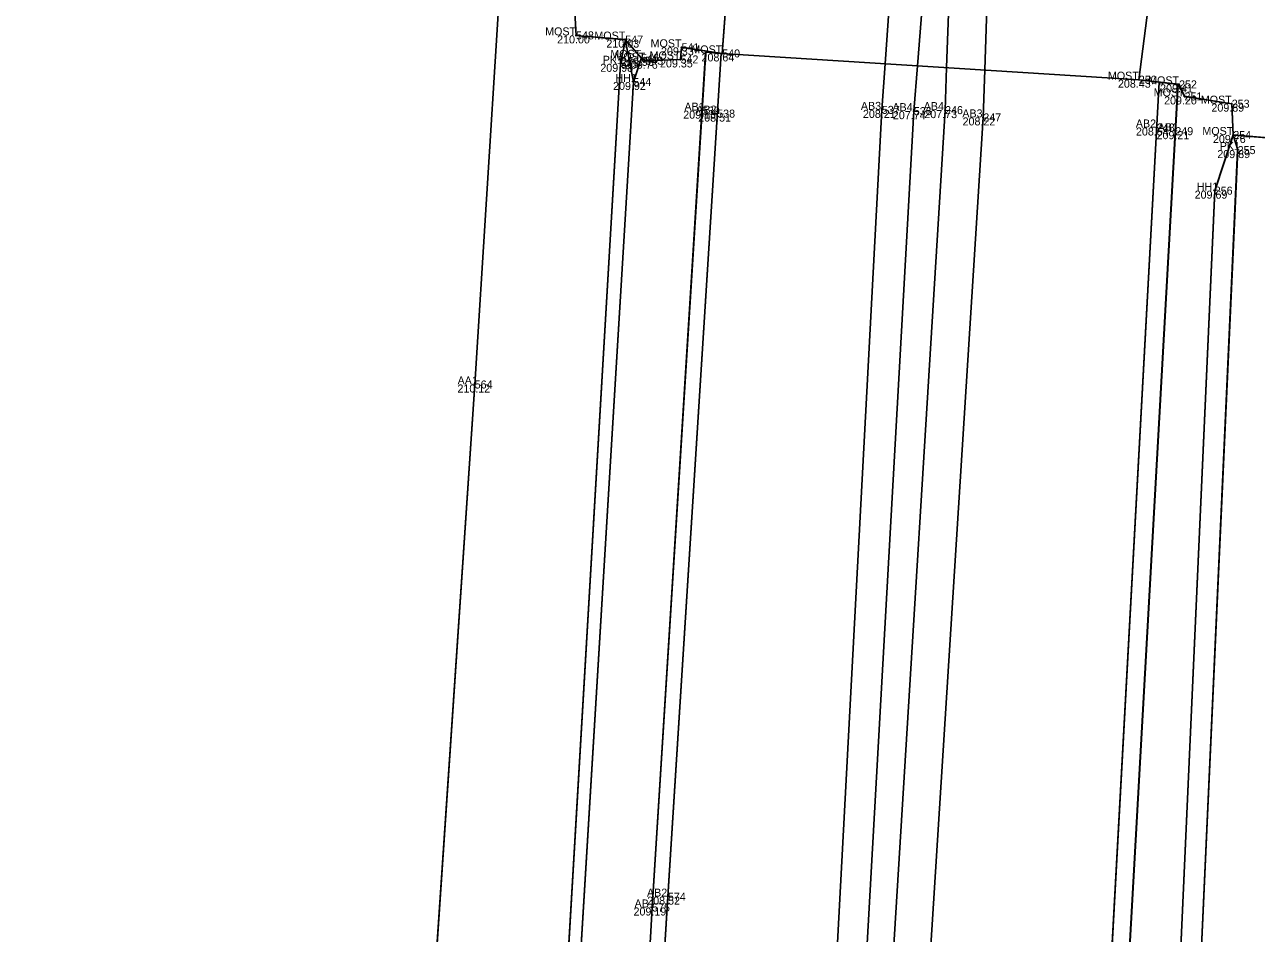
# Model space of a CAD drawing. Extents: x -263091 to -262565, y -1238731 to -1237092.
# Drawn here: x -262850.07 to -262819.29, y -1237957.59 to -1237934.9 of the extents above; entities that cross this region are included whole.
import ezdxf

# ---------------------------------------------------------------- set-up
doc = ezdxf.new("R2010")
doc.units = 0
for name, color, linetype in [('01_Hrana_betónu', 7, 'Continuous'), ('02_Oplotenie', 7, 'Continuous'), ('03_Asfalt', 7, 'Continuous'), ('04_Most', 7, 'Continuous'), ('05_Hrana_terénu', 7, 'Continuous'), ('09_Múrik', 7, 'Continuous'), ('Groma (21)', 7, 'Continuous'), ('Groma (22)', 7, 'Continuous'), ('Groma (23)', 7, 'Continuous'), ('Groma (24)', 7, 'Continuous'), ('U003_Asfalt', 7, 'Continuous'), ('U003_Betónové_múriky', 7, 'Continuous'), ('U003_Betónové_panely', 7, 'Continuous'), ('U003_Ostatné_plochy', 7, 'Continuous'), ('U003_Zeleň_mimo', 7, 'Continuous'), ('U003_Zeleň_vnútro', 7, 'Continuous'), ('U003_Zeleň_zatrávňovač', 7, 'Continuous'), ('U005_Betóny_prídavné', 7, 'Continuous')]:
    doc.layers.add(name, color=color, linetype=linetype)

msp = doc.modelspace()

# ---------------------------------------------------------------- linework, layer by layer
at = {"layer": '01_Hrana_betónu'}
for p, q in [((-262832.51, -1237933.84), (-262832.64, -1237935.62)), ((-262822.231, -1237936.276), (-262822, -1237934.47))]:
    msp.add_line(p, q, dxfattribs=at)
for points in [[(-262828.571, -1237935.876), (-262828.445, -1237934.083)], [(-262827.618, -1237934.133), (-262827.762, -1237935.927)], [(-262826.971, -1237934.173), (-262827.034, -1237935.973)], [(-262826.079, -1237936.033), (-262826.022, -1237934.23)], [(-262832.64, -1237935.62), (-262832.67, -1237935.618)], [(-262903.088, -1238238.797), (-262890.817, -1238204.479), (-262885.468, -1238189.492), (-262878.003, -1238168.56), (-262870.455, -1238147.513), (-262864.947, -1238132.168), (-262859.037, -1238116.651), (-262848.977, -1238095.826), (-262842.353, -1238078.361), (-262839.446, -1238067.823), (-262836.783, -1238055.069), (-262834.905, -1238040.999), (-262833.763, -1238025.462), (-262832.297, -1238000.555), (-262831.13, -1237981.111), (-262829.791, -1237958.391), (-262828.651, -1237937.03), (-262828.571, -1237935.876)], [(-262827.762, -1237935.927), (-262827.853, -1237937.062), (-262829.049, -1237958.415), (-262830.305, -1237981.211), (-262831.433, -1238000.629), (-262832.987, -1238025.43), (-262834.086, -1238041.027), (-262836.169, -1238055.023), (-262838.684, -1238068.024), (-262841.681, -1238078.569), (-262848.285, -1238096.308), (-262858.162, -1238116.913), (-262863.876, -1238132.122), (-262869.919, -1238147.692), (-262877.244, -1238168.638), (-262884.69, -1238189.67), (-262901.991, -1238238.762)], [(-262827.034, -1237935.973), (-262827.072, -1237937.036), (-262828.491, -1237960.168), (-262829.643, -1237980.454), (-262830.754, -1238002.123), (-262832.4, -1238026.024), (-262833.369, -1238041.644), (-262835.263, -1238055.011), (-262838.048, -1238068.261), (-262841.826, -1238081.232), (-262846.645, -1238094.136), (-262857.777, -1238117.273), (-262863.292, -1238131.948), (-262884.082, -1238190.299), (-262901.352, -1238238.742)], [(-262900.376, -1238238.711), (-262890.192, -1238209.46), (-262883.463, -1238190.564), (-262868.512, -1238148.877), (-262862.514, -1238132.276), (-262857.014, -1238117.706), (-262845.846, -1238094.561), (-262841.058, -1238081.49), (-262837.218, -1238068.474), (-262834.492, -1238055.416), (-262832.606, -1238041.772), (-262831.509, -1238026.143), (-262830.024, -1238002.24), (-262828.826, -1237980.518), (-262827.576, -1237960.277), (-262826.117, -1237937.218), (-262826.079, -1237936.033)], [(-262821.719, -1237936.336), (-262822.231, -1237936.276)]]:
    msp.add_lwpolyline(points, dxfattribs=at)
at = {"layer": '02_Oplotenie'}
for points in [[(-262912.451, -1238238.295), (-262908.254, -1238226.663), (-262901.526, -1238207.942), (-262898.552, -1238199.602), (-262894.22, -1238186.327), (-262886.794, -1238165.648), (-262879.297, -1238144.201), (-262873.976, -1238128.814), (-262867.141, -1238113.572), (-262855.316, -1238089.931), (-262850.675, -1238078.807), (-262846.261, -1238065.654), (-262843.56, -1238054.226), (-262842.344, -1238048.099), (-262841.445, -1238040.349), (-262840.733, -1238030.077), (-262839.013, -1238000.384), (-262838.353, -1237989.712), (-262835.178, -1237935.879)], [(-262819.762, -1237938.034), (-262820.788, -1237960.675), (-262821.837, -1237980.919), (-262823.308, -1238002.106), (-262824.582, -1238026.068), (-262825.82, -1238041.973), (-262827.772, -1238056.552), (-262830.57, -1238069.546), (-262834.589, -1238083.855), (-262839.328, -1238095.835), (-262848.782, -1238120.942), (-262853.684, -1238135.175), (-262859.896, -1238152.781), (-262867.698, -1238174.329), (-262874.833, -1238193.487), (-262881.88, -1238212.036), (-262887.174, -1238225.693), (-262888.829, -1238230.138)]]:
    msp.add_lwpolyline(points, dxfattribs=at)
at = {"layer": '03_Asfalt'}
msp.add_lwpolyline([(-262912.678, -1238239.103), (-262913.356, -1238239.285), (-262915.717, -1238239.279), (-262916.328, -1238238.784), (-262916.575, -1238236.319), (-262915.768, -1238233.661), (-262912.404, -1238225.097), (-262904.805, -1238205.606), (-262896.687, -1238184.948), (-262888.478, -1238163.929), (-262880.124, -1238142.63), (-262874.65, -1238128.675), (-262868.549, -1238113.075), (-262858.861, -1238088.481), (-262853.132, -1238074.038), (-262850.084, -1238066.288), (-262845.869, -1238049.471), (-262845.094, -1238038.662), (-262844.346, -1238028.542), (-262842.599, -1238000.955), (-262841.603, -1237985.168), (-262838.824, -1237943.888), (-262838.24, -1237934.633), (-262838.283, -1237933.488)], dxfattribs=at)
at = {"layer": '04_Most'}
msp.add_lwpolyline([(-262837.476, -1237933.537), (-262837.588, -1237934.475), (-262836.324, -1237934.594), (-262836.292, -1237935.17), (-262835.062, -1237935.275), (-262834.664, -1237935.731), (-262834.562, -1237935.803), (-262833.682, -1237935.77), (-262833.657, -1237935.467), (-262832.64, -1237935.62), (-262822.231, -1237936.276), (-262821.226, -1237936.393), (-262821.088, -1237936.694), (-262819.91, -1237936.875), (-262819.871, -1237937.657), (-262818.511, -1237937.77), (-262818.304, -1237934.697)], dxfattribs=at)
at = {"layer": '05_Hrana_terénu'}
for points in [[(-262835.062, -1237935.275), (-262834.86, -1237936.333), (-262838.087, -1237989.633), (-262838.484, -1238000.332), (-262840.387, -1238030.181), (-262840.991, -1238040.253), (-262843.126, -1238054.282), (-262845.675, -1238066.436), (-262850.413, -1238079.623), (-262854.798, -1238090.209), (-262863.856, -1238108.78), (-262866.643, -1238114.502), (-262872.333, -1238129.41), (-262877.981, -1238144.625), (-262885.616, -1238166.033), (-262893.121, -1238186.676), (-262898.244, -1238201.149), (-262900.554, -1238208.001), (-262907.375, -1238226.781), (-262911.85, -1238238.364), (-262912.678, -1238239.103)], [(-262849.564, -1238120.544), (-262839.894, -1238095.583), (-262835.301, -1238083.403), (-262831.402, -1238069.334), (-262828.632, -1238056.516), (-262826.436, -1238041.83), (-262825.08, -1238026.06), (-262823.863, -1238001.967), (-262822.633, -1237980.847), (-262821.298, -1237960.54), (-262820.334, -1237939.047), (-262819.871, -1237937.657)]]:
    msp.add_lwpolyline(points, dxfattribs=at)
at = {"layer": '09_Múrik'}
for points in [[(-262845.277, -1238070.627), (-262844.218, -1238066.744), (-262841.577, -1238054.272), (-262839.647, -1238040.289), (-262838.75, -1238030.675), (-262836.979, -1238000.411), (-262836.237, -1237989.843), (-262834.391, -1237956.949), (-262833.055, -1237935.594)], [(-262844.833, -1238070.767), (-262843.906, -1238066.814), (-262841.249, -1238054.245), (-262839.306, -1238040.158), (-262838.493, -1238030.433), (-262836.614, -1238000.277), (-262836.049, -1237989.856), (-262833.996, -1237956.678), (-262832.67, -1237935.618)], [(-262840.924, -1238094.827), (-262836.941, -1238083.068), (-262832.969, -1238069.042), (-262830.214, -1238056.416), (-262828.063, -1238041.942), (-262826.83, -1238026.465), (-262825.494, -1238001.855), (-262824.316, -1237980.84), (-262823.031, -1237960.337), (-262821.719, -1237936.336)], [(-262840.6, -1238094.732), (-262836.43, -1238082.967), (-262832.633, -1238069.1), (-262829.86, -1238056.421), (-262827.688, -1238042.018), (-262826.338, -1238026.448), (-262825.108, -1238001.872), (-262823.89, -1237980.741), (-262822.602, -1237960.47), (-262821.253, -1237936.39)]]:
    msp.add_lwpolyline(points, dxfattribs=at)
at = {"layer": 'Groma (21)'}
for centre in [(-262836.292, -1237935.17), (-262835.062, -1237935.275), (-262833.657, -1237935.467), (-262832.64, -1237935.62), (-262835.178, -1237935.879), (-262834.664, -1237935.731), (-262834.562, -1237935.803), (-262833.682, -1237935.77), (-262822.231, -1237936.276), (-262834.86, -1237936.333), (-262821.226, -1237936.393), (-262821.088, -1237936.694), (-262819.91, -1237936.875), (-262833.146, -1237937.05), (-262832.765, -1237937.123), (-262828.651, -1237937.03), (-262827.853, -1237937.062), (-262827.072, -1237937.036), (-262826.117, -1237937.218), (-262821.781, -1237937.47), (-262821.319, -1237937.562), (-262819.871, -1237937.657), (-262819.762, -1237938.034), (-262820.334, -1237939.047), (-262838.824, -1237943.888), (-262833.996, -1237956.678), (-262834.391, -1237956.949)]:
    msp.add_circle(centre, 0.01, dxfattribs=at)
at = {"layer": 'U003_Asfalt'}
for points in [[(-262836.86, -1238089.78), (-262834.59, -1238083.86), (-262830.57, -1238069.55), (-262827.77, -1238056.55), (-262825.82, -1238041.97), (-262824.58, -1238026.07), (-262823.31, -1238002.11), (-262821.84, -1237980.92), (-262820.79, -1237960.68), (-262819.76, -1237938.03), (-262819.87, -1237937.66), (-262818.51, -1237937.77), (-262818.3, -1237934.7)], [(-262824.58, -1238026.07), (-262823.31, -1238002.11), (-262821.84, -1237980.92), (-262820.79, -1237960.68), (-262819.76, -1237938.03), (-262819.87, -1237937.66), (-262818.51, -1237937.77), (-262818.3, -1237934.7)]]:
    msp.add_lwpolyline(points, dxfattribs=at)
at = {"layer": 'U003_Betónové_múriky'}
for points in [[(-262834.39, -1237956.95), (-262833.05, -1237935.59), (-262832.67, -1237935.62), (-262834, -1237956.68), (-262836.05, -1237989.86), (-262836.61, -1238000.28), (-262838.49, -1238030.43), (-262839.31, -1238040.16), (-262841.25, -1238054.25), (-262843.91, -1238066.81), (-262844.83, -1238070.77), (-262845.28, -1238070.63), (-262844.22, -1238066.74), (-262841.58, -1238054.27), (-262839.65, -1238040.29), (-262838.75, -1238030.68), (-262836.98, -1238000.41), (-262836.24, -1237989.84)], [(-262821.25, -1237936.39), (-262822.6, -1237960.47), (-262823.89, -1237980.74), (-262825.11, -1238001.87), (-262826.34, -1238026.45), (-262827.69, -1238042.02), (-262829.86, -1238056.42), (-262832.63, -1238069.1), (-262836.43, -1238082.97), (-262840.6, -1238094.73), (-262840.92, -1238094.83), (-262836.94, -1238083.07), (-262832.97, -1238069.04), (-262830.21, -1238056.42), (-262828.06, -1238041.94), (-262826.83, -1238026.47), (-262825.49, -1238001.86), (-262824.32, -1237980.84), (-262823.03, -1237960.34), (-262821.72, -1237936.34)]]:
    msp.add_lwpolyline(points, close=True, dxfattribs=at)
for points in [[(-262836.24, -1237989.84), (-262834.39, -1237956.95), (-262833.05, -1237935.59), (-262832.67, -1237935.62), (-262834, -1237956.68), (-262836.05, -1237989.86), (-262836.61, -1238000.28), (-262838.49, -1238030.43), (-262839.31, -1238040.16), (-262841.25, -1238054.25), (-262843.91, -1238066.81), (-262844.83, -1238070.77), (-262845.28, -1238070.63), (-262844.22, -1238066.74), (-262841.58, -1238054.27), (-262839.65, -1238040.29), (-262838.75, -1238030.68), (-262836.98, -1238000.41), (-262836.24, -1237989.84)], [(-262821.72, -1237936.34), (-262821.25, -1237936.39), (-262822.6, -1237960.47), (-262823.89, -1237980.74), (-262825.11, -1238001.87), (-262826.34, -1238026.45), (-262827.69, -1238042.02), (-262829.86, -1238056.42), (-262832.63, -1238069.1), (-262836.43, -1238082.97), (-262840.6, -1238094.73), (-262840.92, -1238094.83), (-262836.94, -1238083.07), (-262832.97, -1238069.04), (-262830.21, -1238056.42), (-262828.06, -1238041.94), (-262826.83, -1238026.47), (-262825.49, -1238001.86), (-262824.32, -1237980.84), (-262823.03, -1237960.34), (-262821.72, -1237936.34)]]:
    msp.add_lwpolyline(points, dxfattribs=at)
at = {"layer": 'U003_Betónové_panely'}
for points in [[(-262863.7, -1238113.97), (-262862.86, -1238112.21), (-262862.02, -1238109.74), (-262852.53, -1238091.41), (-262847.76, -1238078.52), (-262845.51, -1238070.71), (-262845.28, -1238070.63), (-262844.83, -1238070.77), (-262843.91, -1238066.81), (-262841.25, -1238054.25), (-262839.31, -1238040.16), (-262838.49, -1238030.43), (-262836.61, -1238000.28), (-262836.05, -1237989.86), (-262834, -1237956.68), (-262832.67, -1237935.62), (-262832.64, -1237935.62), (-262832.51, -1237933.84)], [(-262863.7, -1238113.97), (-262862.86, -1238112.21), (-262862.02, -1238109.74), (-262852.53, -1238091.41), (-262847.76, -1238078.52), (-262845.51, -1238070.71), (-262845.28, -1238070.63), (-262844.83, -1238070.77), (-262843.91, -1238066.81), (-262841.25, -1238054.25), (-262839.31, -1238040.16), (-262838.49, -1238030.43), (-262836.61, -1238000.28), (-262836.05, -1237989.86), (-262834, -1237956.68), (-262832.67, -1237935.62), (-262832.64, -1237935.62), (-262832.51, -1237933.84)], [(-262822, -1237934.47), (-262822.23, -1237936.28), (-262821.72, -1237936.34), (-262823.03, -1237960.34), (-262824.32, -1237980.84), (-262825.49, -1238001.86), (-262826.83, -1238026.47), (-262828.06, -1238041.94), (-262830.21, -1238056.42), (-262832.97, -1238069.04), (-262836.94, -1238083.07), (-262840.92, -1238094.83), (-262840.6, -1238094.73), (-262841.76, -1238095.81), (-262851.46, -1238119.84), (-262857.2, -1238134.12), (-262863.32, -1238150.73), (-262871.41, -1238173.11), (-262878.16, -1238192.14), (-262884.61, -1238210.94), (-262889.86, -1238225.24), (-262892.75, -1238232.5), (-262895.19, -1238238.55), (-262900.83, -1238252.4)], [(-262822, -1237934.47), (-262822.23, -1237936.28), (-262821.72, -1237936.34), (-262823.03, -1237960.34), (-262824.32, -1237980.84), (-262825.49, -1238001.86), (-262826.83, -1238026.47), (-262828.06, -1238041.94), (-262830.21, -1238056.42), (-262832.97, -1238069.04), (-262836.94, -1238083.07), (-262840.92, -1238094.83), (-262840.6, -1238094.73), (-262841.76, -1238095.81), (-262851.46, -1238119.84), (-262857.2, -1238134.12), (-262863.32, -1238150.73), (-262871.41, -1238173.11), (-262878.16, -1238192.14), (-262884.61, -1238210.94), (-262889.86, -1238225.24), (-262892.75, -1238232.5), (-262895.19, -1238238.55), (-262900.83, -1238252.4)]]:
    msp.add_lwpolyline(points, dxfattribs=at)
at = {"layer": 'U003_Ostatné_plochy'}
for points in [[(-262832.51, -1237933.84), (-262832.64, -1237935.62), (-262833.66, -1237935.47), (-262833.68, -1237935.77), (-262834.56, -1237935.8), (-262834.66, -1237935.73), (-262835.06, -1237935.28), (-262836.29, -1237935.17), (-262836.32, -1237934.59), (-262837.59, -1237934.48), (-262837.48, -1237933.54)], [(-262818.3, -1237934.7), (-262818.51, -1237937.77), (-262819.87, -1237937.66), (-262819.91, -1237936.88), (-262821.09, -1237936.69), (-262821.23, -1237936.39), (-262822.23, -1237936.28), (-262822, -1237934.47)]]:
    msp.add_lwpolyline(points, close=True, dxfattribs=at)
for points in [[(-262834.56, -1237935.8), (-262834.66, -1237935.73), (-262835.06, -1237935.28), (-262836.29, -1237935.17), (-262836.32, -1237934.59), (-262837.59, -1237934.48), (-262837.48, -1237933.54), (-262832.51, -1237933.84), (-262832.64, -1237935.62), (-262833.66, -1237935.47), (-262833.68, -1237935.77), (-262834.56, -1237935.8)], [(-262818.51, -1237937.77), (-262819.87, -1237937.66), (-262819.91, -1237936.88), (-262821.09, -1237936.69), (-262821.23, -1237936.39), (-262822.23, -1237936.28), (-262822, -1237934.47), (-262818.3, -1237934.7), (-262818.51, -1237937.77)]]:
    msp.add_lwpolyline(points, dxfattribs=at)
at = {"layer": 'U003_Zeleň_mimo'}
for points in [[(-262868.55, -1238113.08), (-262858.86, -1238088.48), (-262853.13, -1238074.04), (-262850.08, -1238066.29), (-262845.87, -1238049.47), (-262845.09, -1238038.66), (-262844.35, -1238028.54), (-262842.6, -1238000.96), (-262841.6, -1237985.17), (-262838.82, -1237943.89), (-262838.24, -1237934.63)], [(-262836.32, -1237934.59), (-262836.29, -1237935.17), (-262835.06, -1237935.28), (-262835.18, -1237935.88), (-262838.35, -1237989.71), (-262839.01, -1238000.38), (-262840.73, -1238030.08), (-262841.45, -1238040.35), (-262842.34, -1238048.1), (-262843.56, -1238054.23), (-262846.26, -1238065.65), (-262850.68, -1238078.81), (-262855.32, -1238089.93), (-262867.14, -1238113.57)]]:
    msp.add_lwpolyline(points, dxfattribs=at)
at = {"layer": 'U003_Zeleň_vnútro'}
for points in [[(-262840.73, -1238030.08), (-262839.01, -1238000.38), (-262838.35, -1237989.71), (-262835.18, -1237935.88), (-262835.06, -1237935.28), (-262834.66, -1237935.73), (-262834.86, -1237936.33), (-262838.09, -1237989.63), (-262838.48, -1238000.33), (-262840.39, -1238030.18)], [(-262840.73, -1238030.08), (-262839.01, -1238000.38), (-262838.35, -1237989.71), (-262835.18, -1237935.88), (-262835.06, -1237935.28), (-262834.66, -1237935.73), (-262834.86, -1237936.33), (-262838.09, -1237989.63), (-262838.48, -1238000.33), (-262840.39, -1238030.18)], [(-262821.09, -1237936.69), (-262821.25, -1237936.39), (-262821.23, -1237936.39), (-262821.09, -1237936.69)], [(-262849.56, -1238120.54), (-262839.89, -1238095.58), (-262835.3, -1238083.4), (-262831.4, -1238069.33), (-262828.63, -1238056.52), (-262826.44, -1238041.83), (-262825.08, -1238026.06), (-262823.86, -1238001.97), (-262822.63, -1237980.85), (-262821.3, -1237960.54), (-262820.33, -1237939.05), (-262819.87, -1237937.66), (-262819.76, -1237938.03), (-262820.79, -1237960.68), (-262821.84, -1237980.92), (-262823.31, -1238002.11), (-262824.58, -1238026.07), (-262825.82, -1238041.97), (-262827.77, -1238056.55), (-262830.57, -1238069.55), (-262834.59, -1238083.86), (-262839.33, -1238095.84), (-262848.78, -1238120.94)], [(-262849.56, -1238120.54), (-262839.89, -1238095.58), (-262835.3, -1238083.4), (-262831.4, -1238069.33), (-262828.63, -1238056.52), (-262826.44, -1238041.83), (-262825.08, -1238026.06), (-262823.86, -1238001.97), (-262822.63, -1237980.85), (-262821.3, -1237960.54), (-262820.33, -1237939.05), (-262819.87, -1237937.66), (-262819.76, -1237938.03), (-262820.79, -1237960.68), (-262821.84, -1237980.92), (-262823.31, -1238002.11), (-262824.58, -1238026.07), (-262825.82, -1238041.97), (-262827.77, -1238056.55), (-262830.57, -1238069.55), (-262834.59, -1238083.86), (-262839.33, -1238095.84), (-262848.78, -1238120.94)]]:
    msp.add_lwpolyline(points, dxfattribs=at)
msp.add_lwpolyline([(-262821.09, -1237936.69), (-262821.25, -1237936.39), (-262821.23, -1237936.39)], close=True, dxfattribs=at)
at = {"layer": 'U003_Zeleň_zatrávňovač'}
for points in [[(-262840.39, -1238030.18), (-262838.48, -1238000.33), (-262838.09, -1237989.63), (-262834.86, -1237936.33), (-262834.66, -1237935.73), (-262834.56, -1237935.8), (-262833.68, -1237935.77), (-262833.66, -1237935.47), (-262832.64, -1237935.62), (-262833.05, -1237935.59), (-262834.39, -1237956.95), (-262836.24, -1237989.84), (-262836.98, -1238000.41), (-262838.75, -1238030.68)], [(-262840.39, -1238030.18), (-262838.48, -1238000.33), (-262838.09, -1237989.63), (-262834.86, -1237936.33), (-262834.66, -1237935.73), (-262834.56, -1237935.8), (-262833.68, -1237935.77), (-262833.66, -1237935.47), (-262832.64, -1237935.62), (-262833.05, -1237935.59), (-262834.39, -1237956.95), (-262836.24, -1237989.84), (-262836.98, -1238000.41), (-262838.75, -1238030.68)], [(-262826.34, -1238026.45), (-262825.11, -1238001.87), (-262823.89, -1237980.74), (-262822.6, -1237960.47), (-262821.25, -1237936.39), (-262821.23, -1237936.39), (-262821.09, -1237936.69), (-262819.91, -1237936.88), (-262819.87, -1237937.66), (-262820.33, -1237939.05), (-262821.3, -1237960.54), (-262822.63, -1237980.85), (-262823.86, -1238001.97), (-262825.08, -1238026.06)]]:
    msp.add_lwpolyline(points, dxfattribs=at)
at = {"layer": 'U005_Betóny_prídavné'}
msp.add_lwpolyline([(-262826.34, -1238026.45), (-262825.11, -1238001.87), (-262823.89, -1237980.74), (-262822.6, -1237960.47), (-262821.25, -1237936.39), (-262821.23, -1237936.39), (-262821.09, -1237936.69), (-262819.91, -1237936.88), (-262819.87, -1237937.66), (-262820.33, -1237939.05), (-262821.3, -1237960.54), (-262822.63, -1237980.85), (-262823.86, -1238001.97), (-262825.08, -1238026.06)], dxfattribs=at)

# ---------------------------------------------------------------- texts
at = {"layer": 'Groma (22)'}
for s, p in [('548', (-262836.292, -1237935.27)), ('547', (-262835.062, -1237935.375)), ('541', (-262833.657, -1237935.567)), ('546', (-262834.664, -1237935.831)), ('542', (-262833.682, -1237935.87)), ('540', (-262832.64, -1237935.72)), ('545', (-262835.178, -1237935.979)), ('543', (-262834.562, -1237935.903)), ('544', (-262834.86, -1237936.433)), ('250', (-262822.231, -1237936.376)), ('252', (-262821.226, -1237936.493)), ('251', (-262821.088, -1237936.794)), ('253', (-262819.91, -1237936.975)), ('539', (-262833.146, -1237937.15)), ('538', (-262832.765, -1237937.223)), ('537', (-262828.651, -1237937.13)), ('536', (-262827.853, -1237937.162)), ('246', (-262827.072, -1237937.136)), ('247', (-262826.117, -1237937.318)), ('248', (-262821.781, -1237937.57)), ('249', (-262821.319, -1237937.662)), ('254', (-262819.871, -1237937.757)), ('255', (-262819.762, -1237938.134)), ('256', (-262820.334, -1237939.147)), ('564', (-262838.824, -1237943.988)), ('574', (-262833.996, -1237956.778)), ('575', (-262834.391, -1237957.049))]:
    msp.add_text(s, height=0.2, dxfattribs=at).set_placement(p)
at = {"layer": 'Groma (23)'}
for s, p in [('210.00', (-262836.764, -1237935.37)), ('210.03', (-262835.534, -1237935.475)), ('209.33', (-262834.169, -1237935.667)), ('208.64', (-262833.157, -1237935.82)), ('209.98', (-262835.685, -1237936.079)), ('209.96', (-262835.166, -1237935.931)), ('209.76', (-262835.07, -1237936.003)), ('209.35', (-262834.194, -1237935.97)), ('208.43', (-262822.752, -1237936.476)), ('209.92', (-262835.367, -1237936.533)), ('209.41', (-262821.699, -1237936.593)), ('209.20', (-262821.599, -1237936.894)), ('209.89', (-262820.417, -1237937.075)), ('209.13', (-262833.614, -1237937.25)), ('208.51', (-262833.238, -1237937.323)), ('208.21', (-262829.124, -1237937.23)), ('207.74', (-262828.376, -1237937.262)), ('207.73', (-262827.59, -1237937.236)), ('208.22', (-262826.634, -1237937.418)), ('208.54', (-262822.302, -1237937.67)), ('209.21', (-262821.787, -1237937.762)), ('209.76', (-262820.379, -1237937.857)), ('209.89', (-262820.269, -1237938.234)), ('209.69', (-262820.836, -1237939.247)), ('210.12', (-262839.254, -1237944.088)), ('208.52', (-262834.513, -1237956.878)), ('209.19', (-262834.855, -1237957.149))]:
    msp.add_text(s, height=0.2, dxfattribs=at).set_placement(p)
at = {"layer": 'Groma (24)'}
for s, p in [('MOST', (-262837.064, -1237935.17)), ('MOST', (-262835.834, -1237935.275)), ('MOST', (-262834.429, -1237935.467)), ('PK1', (-262835.625, -1237935.879)), ('MOST', (-262835.436, -1237935.731)), ('MOST', (-262835.334, -1237935.803)), ('MOST', (-262834.454, -1237935.77)), ('MOST', (-262833.412, -1237935.62)), ('HH1', (-262835.307, -1237936.333)), ('MOST', (-262823.003, -1237936.276)), ('MOST', (-262821.998, -1237936.393)), ('MOST', (-262821.86, -1237936.694)), ('AB1', (-262833.584, -1237937.05)), ('AB2', (-262833.289, -1237937.123)), ('AB3', (-262829.175, -1237937.03)), ('AB4', (-262828.387, -1237937.062)), ('AB4', (-262827.606, -1237937.036)), ('MOST', (-262820.682, -1237936.875)), ('AB3', (-262826.641, -1237937.218)), ('AB2', (-262822.305, -1237937.47)), ('AB1', (-262821.757, -1237937.562)), ('MOST', (-262820.643, -1237937.657)), ('PK1', (-262820.209, -1237938.034)), ('HH1', (-262820.781, -1237939.047)), ('AA1', (-262839.252, -1237943.888)), ('AB2', (-262834.52, -1237956.678)), ('AB1', (-262834.829, -1237956.949))]:
    msp.add_text(s, height=0.2, dxfattribs=at).set_placement(p)

doc.saveas('drawing.dxf')
